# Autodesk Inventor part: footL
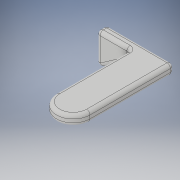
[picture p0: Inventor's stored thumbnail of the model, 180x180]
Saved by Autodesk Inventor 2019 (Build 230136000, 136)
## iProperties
Created: 2020-09
Part Number: footL
Material: 一般
Document SubType Name: Modeling
Designer: kikut
Density: 1 g/cm^3
Appearance: 既定
Author: kikut
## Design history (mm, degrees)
sketch "スケッチ1"
  geometry: L1 (-0.01, -0.1)-(0.01, -0.1); L2 (0.01, -0.1)-(0.01, -0.05); L3 (0.01, -0.05)-(-0.01, -0.05); L4 (-0.01, -0.05)-(-0.01, -0.1); L5 (-0.01, -0.1)-(0.01, -0.05); L6 (0.01, -0.1)-(-0.01, -0.05); L7 (0, -0.12)-(0, 0.02) reference; A1 r 0.01 centre (0, -0.05) between (0.01, -0.05) and (-0.01, -0.05); 2 further points
  constraints: 12 end point, 4 midpoint, 2 parallel, 2 point on circle, 1 centre point, 1 horizontal, 1 perpendicular, 1 other
  dimensions: "d0" = 0.05 distance of L1.end L2.end; "d1" = 0.05 distance from line of L3 point (0, 0); "d2" = 0.02 distance of L2.end L3.end
extrude "押し出し1" new body sketch "スケッチ1" stored distance "d3" = 0.006; taper "d4" = 0 deg
sketch "スケッチ3"
  geometry: L1 (0.02, 0)-(0, 0) reference; L2 (0.02, 0)-(0.04, 0); L3 (0.04, 0)-(0.04, -0.02); L4 (0, -0.006)-(0.02, -0.006) reference; L5 (0.04, -0.02)-(0.02, -0.006); L6 (0.02, -0.006)-(0.02, 0); 1 further point
  constraints: 8 end point, 1 horizontal, 1 parallel, 1 perpendicular
  dimensions: "d10" = 0.02 distance of L1.start L2.end; "d11" = 0.02 distance of L2.end L3.end
extrude "押し出し3" join sketch "スケッチ3" distance "d12" = 0.006; taper "d13" = 0 deg
fillet "フィレット2" dims "d14" = 0.002
fillet "フィレット3" dims "d15" = 0.002
fillet "フィレット4" dims "d16" = 0.002
node "ソリッド1"
